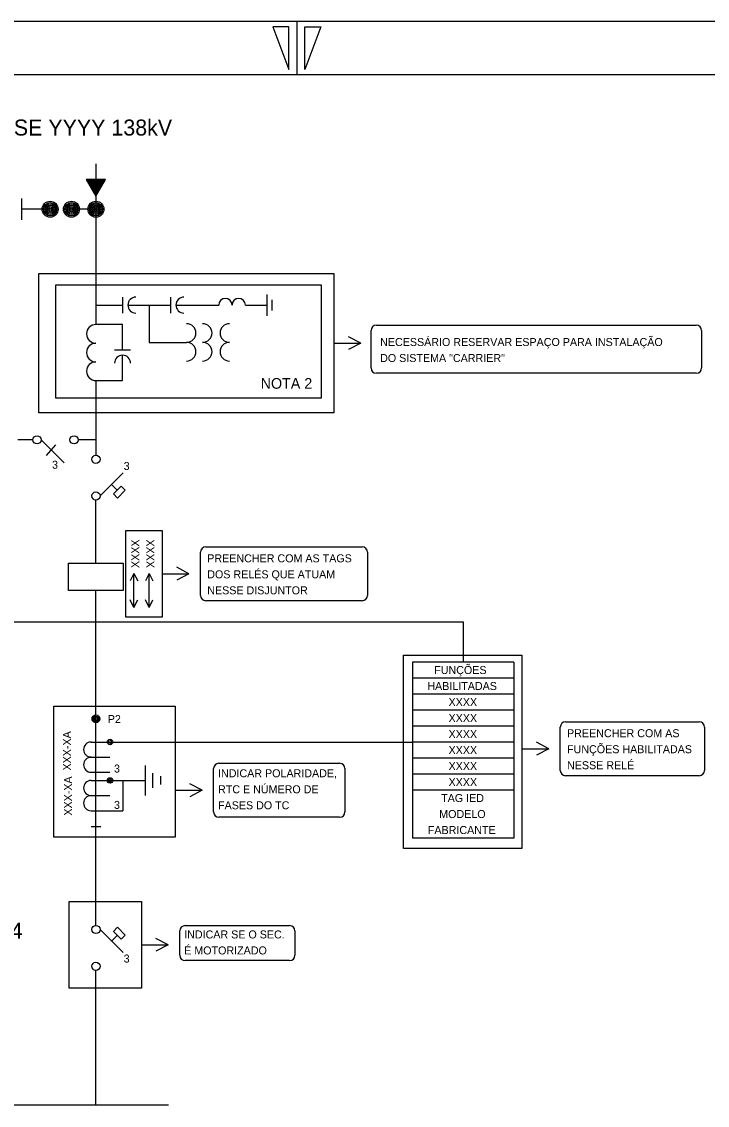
# Model space of a CAD drawing. Extents: x 400 to 1404, y 358 to 952.
# Drawn here: x 982 to 1110.5, y 748.8 to 952 of the extents above; entities that cross this region are included whole.
import ezdxf

# ---------------------------------------------------------------- set-up
doc = ezdxf.new("R2010")
doc.units = 0
doc.layers.add('Level 1', color=7, linetype='Continuous')
doc.layers.add('New Level (0)', color=7, linetype='Continuous')

msp = doc.modelspace()

# ---------------------------------------------------------------- linework, layer by layer
for p, q in [((995.93, 925.28), (995.93, 895.18)), ((997.74, 922.35), (994.12, 922.35)), ((994.12, 922.35), (995.93, 919.25)), ((997.74, 922.35), (994.12, 922.35)), ((995.93, 919.25), (997.74, 922.35)), ((995.93, 922.35), (995.93, 919.25)), ((997.56, 922.25), (994.31, 922.25)), ((994.31, 922.25), (995.93, 919.46)), ((997.38, 922.14), (994.49, 922.14)), ((994.49, 922.14), (995.93, 919.67)), ((997.2, 922.04), (994.67, 922.04)), ((994.67, 922.04), (995.93, 919.87)), ((997.02, 921.94), (994.85, 921.94)), ((994.85, 921.94), (995.93, 920.08)), ((996.84, 921.83), (995.03, 921.83)), ((995.03, 921.83), (995.93, 920.29)), ((996.66, 921.73), (995.21, 921.73)), ((995.21, 921.73), (995.93, 920.49)), ((996.48, 921.63), (995.39, 921.63)), ((995.39, 921.63), (995.93, 920.7)), ((996.3, 921.52), (995.57, 921.52)), ((995.57, 921.52), (995.93, 920.9)), ((996.12, 921.42), (995.75, 921.42)), ((995.75, 921.42), (995.93, 921.11)), ((995.93, 919.46), (997.56, 922.25)), ((995.93, 919.67), (997.38, 922.14)), ((995.93, 919.87), (997.2, 922.04)), ((995.93, 920.08), (997.02, 921.94)), ((995.93, 920.29), (996.84, 921.83)), ((995.93, 920.49), (996.66, 921.73)), ((995.93, 920.7), (996.48, 921.63)), ((995.93, 920.9), (996.3, 921.52)), ((995.93, 921.11), (996.12, 921.42)), ((982.03, 914.8), (982.03, 918.8)), ((983.35, 916.8), (982.03, 916.8)), ((987.35, 916.8), (983.35, 916.8)), ((995.93, 916.8), (991.35, 916.8)), ((995.93, 884.68), (995.93, 870.68)), ((984.13, 873.56), (981.33, 873.56)), ((990, 869.23), (985.66, 873.56)), ((986.65, 870.62), (988.45, 872.64)), ((995.93, 873.56), (992.6, 873.56)), ((1001.04, 867.38), (996.7, 863.05)), ((999.93, 864.15), (998.87, 865.21)), ((995.93, 850.41), (995.93, 862.24)), ((990.81, 845.29), (990.81, 850.41)), ((990.81, 850.41), (1001.05, 850.41)), ((1001.05, 850.41), (1001.05, 845.29)), ((1003.05, 848.53), (1002.34, 847.11)), ((1003.05, 842.16), (1003.05, 848.53)), ((1003.05, 848.53), (1003.76, 847.11)), ((1005.9, 848.53), (1005.19, 847.11)), ((1005.9, 842.16), (1005.9, 848.53)), ((1005.9, 848.53), (1006.61, 847.11)), ((1001.05, 845.29), (990.81, 845.29)), ((995.93, 782.54), (995.93, 845.29)), ((1003.05, 842.16), (1002.34, 843.57)), ((1003.05, 842.16), (1003.76, 843.57)), ((1005.9, 842.16), (1005.19, 843.57)), ((1005.9, 842.16), (1006.61, 843.57)), ((1074.23, 831.91), (1055.25, 831.91)), ((1055.25, 831.91), (1055.25, 798.91)), ((1074.23, 831.91), (1074.23, 798.91)), ((1074.23, 828.91), (1055.25, 828.91)), ((1074.23, 825.91), (1055.25, 825.91)), ((1074.23, 822.91), (1055.25, 822.91)), ((1074.23, 819.91), (1055.25, 819.91)), ((995.03, 816.91), (998.56, 816.91)), ((998.56, 816.91), (1055.25, 816.91)), ((1074.23, 816.91), (1055.25, 816.91)), ((995.03, 814.08), (998.56, 814.08)), ((1074.23, 813.91), (1055.25, 813.91)), ((1074.23, 813.91), (1055.25, 813.91)), ((995.03, 811.25), (998.56, 811.25)), ((1005.17, 812.5), (1005.17, 806.91)), ((1006.57, 808.31), (1006.57, 811.1)), ((1074.23, 810.91), (1055.25, 810.91)), ((995.03, 809.7), (998.56, 809.7)), ((996.8, 809.7), (1005.17, 809.7)), ((1008.05, 810.48), (1008.05, 808.93)), ((995.03, 806.87), (998.56, 806.87)), ((1074.23, 807.91), (1055.25, 807.91)), ((995.03, 804.04), (1000.98, 804.04)), ((1074.23, 798.91), (1055.25, 798.91)), ((1001.04, 777.43), (996.7, 781.77)), ((999.93, 780.66), (998.87, 779.6)), ((995.93, 748.8), (995.93, 774.1)), ((1009.5, 748.8), (807.64, 748.8))]:
    msp.add_line(p, q)
for points in [[(999.96, 862.65), (999.2, 863.42), (1000.67, 864.89), (1001.44, 864.12)], [(999.96, 782.17), (999.2, 781.4), (1000.67, 779.93), (1001.44, 780.69)]]:
    msp.add_lwpolyline(points, close=True)
for centre, radius in [((987.35, 916.8), 1.5), ((991.35, 916.8), 1.5), ((995.93, 916.8), 1.5), ((987.35, 916.8), 1.25), ((987.35, 916.8), 1), ((987.35, 916.8), 0.75), ((987.35, 916.8), 0.5), ((987.35, 916.8), 0.25), ((991.35, 916.8), 1.25), ((991.35, 916.8), 1), ((991.35, 916.8), 0.75), ((991.35, 916.8), 0.5), ((991.35, 916.8), 0.25), ((995.93, 916.8), 1.25), ((995.93, 916.8), 1), ((995.93, 916.8), 0.75), ((995.93, 916.8), 0.5), ((995.93, 916.8), 0.25), ((984.9, 873.56), 0.768), ((991.84, 873.56), 0.768), ((995.93, 869.92), 0.768), ((995.93, 863.05), 0.768), ((995.93, 821.25), 0.729), ((995.93, 821.24), 0.511), ((995.93, 821.24), 0.288), ((998.57, 816.91), 0.511), ((998.57, 816.91), 0.288), ((998.57, 809.7), 0.511), ((998.57, 809.7), 0.288), ((995.93, 781.77), 0.768), ((995.93, 774.87), 0.768)]:
    msp.add_circle(centre, radius)
for centre in [(995.03, 815.49), (995.03, 812.66), (995.03, 808.29), (995.03, 805.46)]:
    msp.add_arc(centre, 1.42, 90, 270)
at = {"layer": 'Level 1'}
for p, q in [((1000.93, 900.33), (1000.93, 897.33)), ((1009.93, 900.33), (1009.93, 897.33)), ((1027.93, 900.83), (1027.93, 896.83)), ((995.93, 898.83), (1000.93, 898.83)), ((1001.93, 898.83), (1009.93, 898.83)), ((1005.93, 898.83), (1005.93, 891.83)), ((1010.93, 898.83), (1018.93, 898.83)), ((1023.93, 898.83), (1027.93, 898.83)), ((1028.93, 897.83), (1028.93, 899.83)), ((1029.93, 898.83), (1029.93, 898.83)), ((1000.93, 895.18), (995.93, 895.18)), ((1000.93, 890.43), (1000.93, 895.18)), ((999.43, 890.43), (1002.43, 890.43)), ((1005.93, 891.83), (1012.93, 891.83)), ((1000.93, 884.68), (1000.93, 889.43)), ((995.93, 884.68), (1000.93, 884.68))]:
    msp.add_line(p, q, dxfattribs=at)
for centre, radius, start, end in [((1003.43, 898.83), 1.5, 90, 270), ((1012.43, 898.83), 1.5, 90, 270), ((1020.18, 898.83), 1.25, 0, 180), ((1022.68, 898.83), 1.25, 0, 180), ((995.93, 893.43), 1.75, 90, 270), ((1012.93, 893.58), 1.75, 270, 90), ((1015.93, 893.58), 1.75, 270, 90), ((1020.93, 893.58), 1.75, 90, 270), ((995.93, 889.93), 1.75, 90, 270), ((1012.93, 890.08), 1.75, 270, 90), ((1015.93, 890.08), 1.75, 270, 90), ((1020.93, 890.08), 1.75, 90, 270), ((995.93, 886.43), 1.75, 90, 270), ((1000.93, 887.93), 1.5, 0, 180)]:
    msp.add_arc(centre, radius, start, end, dxfattribs=at)
at = {"layer": 'New Level (0)'}
for p, q in [((1403.58, 951.96), (562.58, 951.96)), ((1403.58, 951.96), (562.58, 951.96)), ((1032.08, 950.96), (1029.08, 950.96)), ((1029.08, 950.96), (1032.08, 942.96)), ((1032.08, 942.96), (1032.08, 950.96)), ((1033.58, 951.96), (1033.58, 941.96)), ((1035.08, 942.96), (1035.08, 950.96)), ((1035.08, 950.96), (1038.08, 950.96)), ((1038.08, 950.96), (1035.08, 942.96)), ((1393.58, 941.96), (572.58, 941.96)), ((1047.47, 887.03), (1047.47, 894.06)), ((1048.47, 895.06), (1078.55, 895.06)), ((1078.55, 895.06), (1108.42, 895.06)), ((1109.42, 894.06), (1109.42, 887.03)), ((1045.56, 891.68), (1043.26, 892.89)), ((1040.53, 891.68), (1045.56, 891.68)), ((1045.56, 891.68), (1043.26, 890.48)), ((1108.42, 886.03), (1048.47, 886.03)), ((1016.53, 853.51), (1023.88, 853.51)), ((1023.88, 853.51), (1045.82, 853.51)), ((1015.53, 844.4), (1015.53, 852.51)), ((1046.82, 852.51), (1046.82, 844.4)), ((1013.37, 848.45), (1011.07, 849.66)), ((1008.34, 848.45), (1013.37, 848.45)), ((1013.37, 848.45), (1011.07, 847.24)), ((1045.82, 843.4), (1016.53, 843.4)), ((893.86, 839.44), (1064.74, 839.44)), ((1064.74, 839.44), (1064.74, 831.91)), ((1082.94, 811.6), (1082.94, 819.71)), ((1083.94, 820.71), (1091.29, 820.71)), ((1091.29, 820.71), (1108.95, 820.71)), ((1109.95, 819.71), (1109.95, 811.6)), ((1080.78, 815.66), (1078.48, 816.87)), ((1075.75, 815.66), (1080.78, 815.66)), ((1080.78, 815.66), (1078.48, 814.45)), ((1018.98, 812.92), (1026.33, 812.92)), ((1026.33, 812.92), (1041.59, 812.92)), ((1017.98, 803.8), (1017.98, 811.92)), ((1042.59, 811.92), (1042.59, 803.8)), ((1108.95, 810.6), (1083.94, 810.6)), ((1000.98, 809.7), (1000.98, 804.04)), ((1015.82, 807.86), (1013.52, 809.07)), ((1010.79, 807.86), (1015.82, 807.86)), ((1015.82, 807.86), (1013.52, 806.65)), ((1041.59, 802.8), (1018.98, 802.8)), ((995.04, 801.09), (996.84, 801.09)), ((1012.64, 782.49), (1019.99, 782.49)), ((1019.99, 782.49), (1032.22, 782.49)), ((1011.64, 776.93), (1011.64, 781.49)), ((1033.22, 781.49), (1033.22, 776.93)), ((1004.45, 778.89), (1009.48, 778.89)), ((1009.48, 778.89), (1007.18, 780.1)), ((1009.48, 778.89), (1007.18, 777.68)), ((1032.22, 775.93), (1012.64, 775.93))]:
    msp.add_line(p, q, dxfattribs=at)
for points in [[(985.25, 904.74), (1040.53, 904.74), (1040.53, 878.63), (985.25, 878.63)], [(988.39, 902.64), (1038.14, 902.64), (1038.14, 881.36), (988.39, 881.36)], [(1001.56, 856.56), (1008.34, 856.56), (1008.34, 840.34), (1001.56, 840.34)], [(1053.56, 833.21), (1075.75, 833.21), (1075.75, 796.96), (1053.56, 796.96)], [(988.06, 823.65), (1010.79, 823.65), (1010.79, 799.07), (988.06, 799.07)], [(990.89, 787), (1004.45, 787), (1004.45, 770.78), (990.89, 770.78)]]:
    msp.add_lwpolyline(points, close=True, dxfattribs=at)
for centre, start, end in [((1048.47, 894.06), 90, 180), ((1108.42, 894.06), 0, 90), ((1048.47, 887.03), 180, 270), ((1108.42, 887.03), 270, 0), ((1016.53, 852.51), 90, 180), ((1045.82, 852.51), 0, 90), ((1016.53, 844.4), 180, 270), ((1045.82, 844.4), 270, 0), ((1083.94, 819.71), 90, 180), ((1108.95, 819.71), 0, 90), ((1018.98, 811.92), 90, 180), ((1041.59, 811.92), 0, 90), ((1083.94, 811.6), 180, 270), ((1108.95, 811.6), 270, 0), ((1018.98, 803.8), 180, 270), ((1041.59, 803.8), 270, 0), ((1012.64, 781.49), 90, 180), ((1032.22, 781.49), 0, 90), ((1012.64, 776.93), 180, 270), ((1032.22, 776.93), 270, 0)]:
    msp.add_arc(centre, 1, start, end, dxfattribs=at)

# ---------------------------------------------------------------- texts
for s, height, p in [('SE YYYY 138kV', 3, (980.55, 930.61)), ('NECESSÁRIO RESERVAR ESPAÇO PARA INSTALAÇÃO ', 1.5, (1049.18, 891.15)), ('DO SISTEMA "CARRIER"', 1.5, (1049.18, 888.15)), ('NOTA 2', 2, (1026.8, 883.14)), ('3', 1.5, (987.71, 868.14)), ('3', 1.5, (1001.13, 867.91)), ('PREENCHER COM AS TAGS ', 1.5, (1016.79, 850.6)), ('DOS RELÉS QUE ATUAM ', 1.5, (1016.79, 847.6)), ('NESSE DISJUNTOR', 1.5, (1016.79, 844.6)), ('FUNÇÕES ', 1.5, (1059.31, 829.66)), ('HABILITADAS', 1.5, (1058.02, 826.66)), ('XXXX', 1.5, (1062, 823.66)), ('P2', 1.5, (998.15, 820.47)), ('XXXX', 1.5, (1062, 820.66)), ('XXXX', 1.5, (1062, 817.66)), ('PREENCHER COM AS ', 1.5, (1084.2, 817.81)), ('FUNÇÕES HABILITADAS ', 1.5, (1084.2, 814.81)), ('XXXX', 1.5, (1062, 814.66)), ('3', 1.5, (999.32, 811.19)), ('XXXX', 1.5, (1062, 811.66)), ('NESSE RELÉ', 1.5, (1084.2, 811.81)), ('INDICAR POLARIDADE, ', 1.5, (1018.81, 810.3)), ('RTC E NÚMERO DE ', 1.5, (1018.81, 807.3)), ('XXXX', 1.5, (1062, 808.66)), ('TAG IED', 1.5, (1060.61, 805.66)), ('3', 1.5, (999.32, 804.37)), ('FASES DO TC', 1.5, (1018.81, 804.3)), ('MODELO', 1.5, (1060.25, 802.66)), ('FABRICANTE', 1.5, (1058.12, 799.66)), ('SEC4', 3, (971.72, 780.04)), ('INDICAR SE O SEC. ', 1.5, (1012.47, 780.09)), ('É MOTORIZADO', 1.5, (1012.47, 777.09)), ('3', 1.5, (1001.13, 775.57))]:
    msp.add_text(s, height=height).set_placement(p)
for s, p in [('XXXX', (1004.05, 849.53)), ('XXXX', (1006.9, 849.53)), ('XXX-XA', (991.26, 811.57)), ('XXX-XA', (991.46, 803.11))]:
    msp.add_text(s, height=1.5, rotation=90).set_placement(p)

doc.saveas('drawing.dxf')
